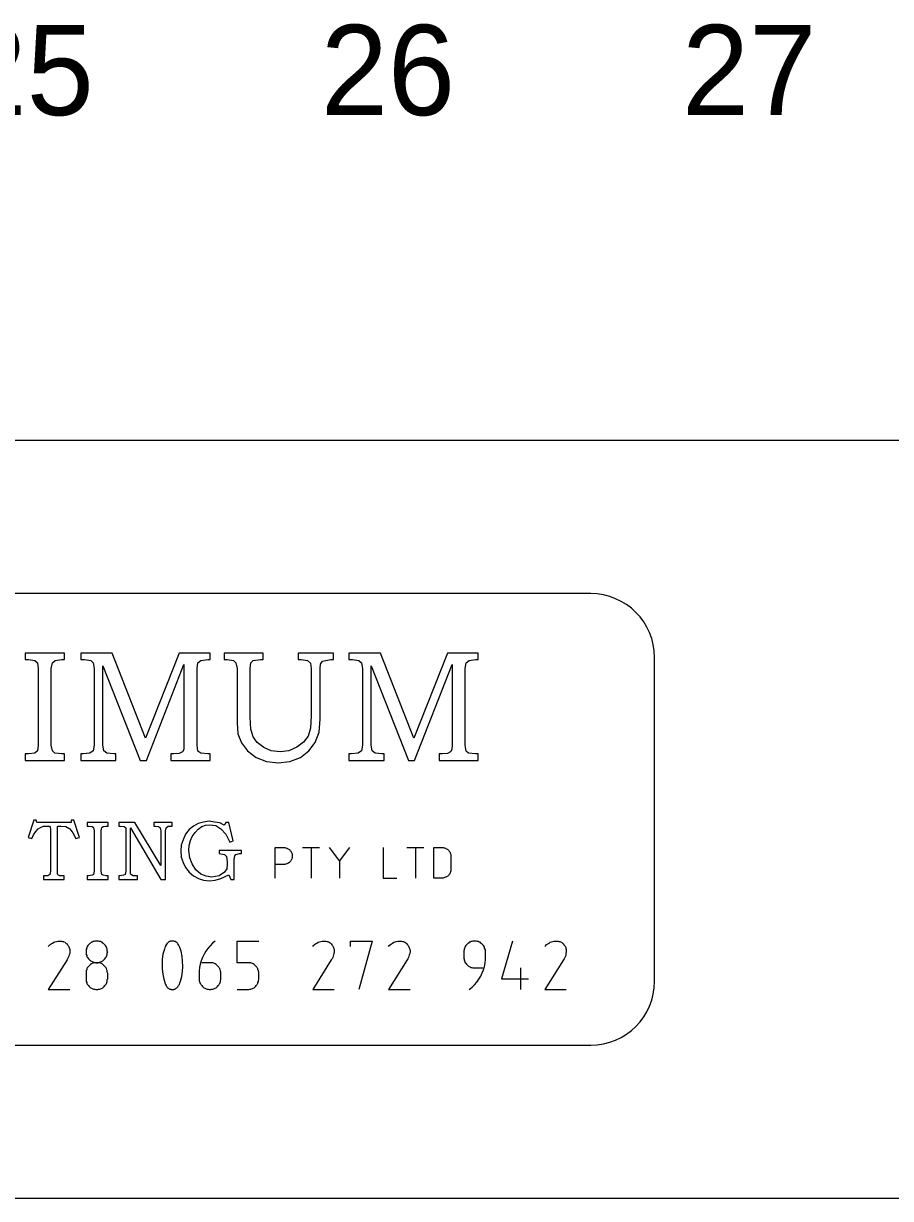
# Model space of a CAD drawing. Extents: x 0 to 841, y 0 to 594.
# Drawn here: x 540.1 to 588.1, y 15 to 80.1 of the extents above; entities that cross this region are included whole.
import ezdxf

# ---------------------------------------------------------------- set-up
doc = ezdxf.new("R2010")
doc.units = 0
for name, color, linetype in [('A1BORDER', 7, 'Continuous'), ('Level 1', 7, 'Continuous'), ('Level 10', 7, 'Continuous')]:
    doc.layers.add(name, color=color, linetype=linetype)

msp = doc.modelspace()

# ---------------------------------------------------------------- linework, layer by layer
at = {"layer": 'A1BORDER'}
for p, q in [((28, 57), (829, 57)), ((829, 15), (28, 15))]:
    msp.add_line(p, q, dxfattribs=at)
at = {"layer": 'Level 1'}
for points in [[(540.64, 35.95), (540.32, 35), (540.52, 34.93), (540.62, 35.15), (540.74, 35.33), (540.87, 35.47), (541, 35.55), (541.17, 35.63), (541.38, 35.63), (541.49, 35.63), (541.53, 35.57), (541.56, 35.45), (541.56, 33.13), (541.52, 32.95), (541.4, 32.87), (541.16, 32.87), (541.16, 32.67), (542.32, 32.67), (542.32, 32.87), (542.08, 32.87), (541.99, 32.9), (541.94, 32.97), (541.94, 33.13), (541.94, 35.43), (541.94, 35.6), (541.97, 35.63), (542.12, 35.63), (542.4, 35.6), (542.63, 35.47), (542.8, 35.25), (542.96, 34.93), (543.16, 35), (542.84, 35.95), (542.7, 35.95), (542.69, 35.83), (540.79, 35.83), (540.77, 35.95)], [(543.59, 35.83), (543.59, 35.63), (543.68, 35.63), (543.87, 35.6), (543.94, 35.55), (543.97, 35.37), (543.97, 33.13), (543.94, 32.95), (543.87, 32.9), (543.68, 32.87), (543.59, 32.87), (543.59, 32.67), (544.74, 32.67), (544.74, 32.87), (544.64, 32.87), (544.47, 32.9), (544.39, 32.95), (544.36, 33.13), (544.36, 35.37), (544.39, 35.55), (544.47, 35.6), (544.64, 35.63), (544.74, 35.63), (544.74, 35.83)], [(545.34, 35.83), (545.34, 35.63), (545.42, 35.63), (545.64, 35.6), (545.72, 35.53), (545.73, 35.37), (545.73, 33.13), (545.69, 32.95), (545.6, 32.9), (545.39, 32.87), (545.34, 32.87), (545.34, 32.67), (546.37, 32.67), (546.37, 32.87), (546.14, 32.87), (546.04, 32.93), (545.99, 32.97), (545.98, 33.13), (545.98, 35.53), (547.66, 32.67), (547.92, 32.67), (547.92, 35.37), (547.96, 35.53), (548.06, 35.63), (548.24, 35.63), (548.29, 35.63), (548.29, 35.83), (547.27, 35.83), (547.27, 35.63), (547.36, 35.63), (547.53, 35.6), (547.62, 35.53), (547.66, 35.37), (547.66, 33.45), (546.23, 35.83)], [(551.26, 35.83), (551.16, 35.67), (550.93, 35.8), (550.64, 35.85), (550.33, 35.9), (550.02, 35.85), (549.73, 35.77), (549.47, 35.63), (549.23, 35.43), (549.03, 35.17), (548.89, 34.87), (548.79, 34.57), (548.77, 34.25), (548.79, 33.9), (548.89, 33.6), (549.03, 33.33), (549.24, 33.07), (549.48, 32.87), (549.74, 32.73), (550.03, 32.63), (550.36, 32.6), (550.67, 32.63), (550.99, 32.73), (551.42, 32.93), (551.54, 32.67), (551.73, 32.67), (551.73, 33.77), (551.76, 33.97), (551.82, 34.05), (552.02, 34.1), (552.12, 34.1), (552.12, 34.27), (550.89, 34.27), (550.89, 34.1), (551.19, 34.05), (551.3, 33.95), (551.34, 33.67), (551.34, 33.53), (551.32, 33.25), (551.19, 33.07), (550.89, 32.87), (550.69, 32.83), (550.48, 32.8), (550.17, 32.85), (549.87, 32.97), (549.6, 33.2), (549.39, 33.53), (549.27, 33.87), (549.22, 34.27), (549.24, 34.55), (549.3, 34.83), (549.4, 35.05), (549.56, 35.27), (549.73, 35.45), (549.93, 35.6), (550.14, 35.67), (550.38, 35.7), (550.7, 35.65), (550.99, 35.47), (551.26, 35.17), (551.48, 34.73), (551.67, 34.8), (551.42, 35.83)]]:
    msp.add_lwpolyline(points, close=True, dxfattribs=at)
for points in [[(554, 32.75), (554, 34.44), (554.48, 34.44), (554.52, 34.44), (554.56, 34.43), (554.59, 34.43), (554.64, 34.41), (554.67, 34.39), (554.7, 34.37), (554.74, 34.35), (554.78, 34.33), (554.8, 34.3), (554.83, 34.26), (554.86, 34.24), (554.88, 34.2), (554.9, 34.16), (554.92, 34.13), (554.93, 34.09), (554.94, 34.05), (554.94, 34.01), (554.94, 33.97), (554.94, 33.93), (554.94, 33.89), (554.93, 33.85), (554.92, 33.81), (554.9, 33.77), (554.88, 33.74), (554.86, 33.7), (554.83, 33.67), (554.8, 33.64), (554.78, 33.61), (554.74, 33.59), (554.7, 33.56), (554.67, 33.55), (554.64, 33.53), (554.59, 33.51), (554.56, 33.51), (554.52, 33.5), (554.48, 33.5), (554, 33.5)], [(555.5, 34.44), (556.44, 34.44)], [(555.98, 34.44), (555.98, 32.75)], [(556.99, 34.44), (557.56, 33.69), (558.12, 34.44)], [(559.98, 34.44), (559.98, 32.75), (560.73, 32.75)], [(561.29, 34.44), (562.23, 34.44)], [(561.77, 34.44), (561.77, 32.75)], [(562.78, 32.75), (562.78, 34.44), (563.26, 34.44), (563.29, 34.44), (563.33, 34.43), (563.37, 34.43), (563.42, 34.41), (563.44, 34.39), (563.48, 34.37), (563.52, 34.35), (563.56, 34.33), (563.58, 34.3), (563.6, 34.26), (563.63, 34.24), (563.66, 34.2), (563.68, 34.16), (563.69, 34.13), (563.7, 34.09), (563.72, 34.05), (563.72, 34.01), (563.72, 33.97), (563.72, 33.23), (563.72, 33.17), (563.72, 33.14), (563.7, 33.1), (563.69, 33.06), (563.68, 33.03), (563.66, 32.99), (563.63, 32.95), (563.6, 32.93), (563.58, 32.89), (563.56, 32.86), (563.52, 32.84), (563.48, 32.81), (563.44, 32.8), (563.42, 32.79), (563.37, 32.77), (563.33, 32.76), (563.29, 32.75), (563.26, 32.75), (562.78, 32.75)], [(557.56, 33.69), (557.56, 32.75)], [(541.43, 28.96), (541.48, 29.01), (541.53, 29.07), (541.59, 29.11), (541.67, 29.15), (541.73, 29.19), (541.8, 29.21), (541.88, 29.24), (541.96, 29.25), (542.03, 29.26), (542.07, 29.26), (542.12, 29.26), (542.17, 29.25), (542.22, 29.24), (542.27, 29.23), (542.3, 29.21), (542.36, 29.19), (542.39, 29.16), (542.43, 29.13), (542.47, 29.1), (542.49, 29.05), (542.53, 29.01), (542.56, 28.97), (542.57, 28.94), (542.59, 28.89), (542.6, 28.84), (542.62, 28.79), (542.62, 28.75), (542.62, 28.7), (542.62, 28.66), (542.62, 28.57), (542.59, 28.5), (542.57, 28.43), (542.54, 28.35), (542.5, 28.27), (542.48, 28.21), (541.43, 26.57), (542.62, 26.57)], [(544.12, 28.06), (544.17, 28.06), (544.22, 28.07), (544.27, 28.09), (544.32, 28.1), (544.37, 28.13), (544.42, 28.15), (544.46, 28.17), (544.49, 28.2), (544.53, 28.24), (544.57, 28.27), (544.6, 28.33), (544.63, 28.36), (544.66, 28.41), (544.68, 28.46), (544.69, 28.51), (544.7, 28.56), (544.7, 28.61), (544.72, 28.66), (544.7, 28.71), (544.7, 28.77), (544.69, 28.81), (544.68, 28.86), (544.66, 28.91), (544.63, 28.96), (544.6, 29.01), (544.57, 29.05), (544.53, 29.09), (544.49, 29.13), (544.46, 29.15), (544.42, 29.19), (544.37, 29.2), (544.32, 29.23), (544.27, 29.24), (544.22, 29.25), (544.17, 29.26), (544.12, 29.26), (544.07, 29.26), (544, 29.25), (543.96, 29.24), (543.9, 29.23), (543.86, 29.2), (543.82, 29.19), (543.77, 29.15), (543.73, 29.13), (543.69, 29.09), (543.66, 29.05), (543.62, 29.01), (543.59, 28.96), (543.57, 28.91), (543.56, 28.86), (543.53, 28.81), (543.53, 28.77), (543.52, 28.71), (543.52, 28.66), (543.52, 28.61), (543.53, 28.56), (543.53, 28.51), (543.56, 28.46), (543.57, 28.41), (543.59, 28.36), (543.62, 28.33), (543.66, 28.27), (543.69, 28.24), (543.73, 28.2), (543.77, 28.17), (543.82, 28.15), (543.86, 28.13), (543.9, 28.1), (543.96, 28.09), (544, 28.07), (544.07, 28.06), (544.12, 28.06)], [(548, 26.73), (548.02, 26.7), (548.04, 26.67), (548.07, 26.65), (548.09, 26.64), (548.12, 26.61), (548.16, 26.6), (548.18, 26.59), (548.22, 26.59), (548.24, 26.57), (548.28, 26.57), (548.3, 26.57), (548.34, 26.57), (548.38, 26.57), (548.4, 26.59), (548.43, 26.6), (548.47, 26.61), (548.49, 26.63), (548.52, 26.65), (548.54, 26.66), (548.57, 26.69), (548.59, 26.71), (548.6, 26.73), (548.64, 26.79), (548.69, 26.86), (548.72, 26.94), (548.76, 27.03), (548.82, 27.3), (548.86, 27.57), (548.88, 27.85), (548.87, 28.14), (548.84, 28.41), (548.78, 28.69), (548.76, 28.81), (548.72, 28.9), (548.68, 28.97), (548.64, 29.05), (548.6, 29.11), (548.58, 29.14), (548.56, 29.16), (548.53, 29.19), (548.5, 29.2), (548.48, 29.23), (548.44, 29.24), (548.42, 29.24), (548.38, 29.25), (548.36, 29.26), (548.32, 29.26), (548.29, 29.26), (548.26, 29.26), (548.23, 29.25), (548.19, 29.25), (548.17, 29.24), (548.13, 29.23), (548.1, 29.21), (548.08, 29.19), (548.06, 29.17), (548.03, 29.15), (548, 29.13), (548, 29.11), (547.96, 29.05), (547.9, 28.96), (547.88, 28.89), (547.86, 28.81), (547.78, 28.54), (547.74, 28.26), (547.73, 27.97), (547.73, 27.7), (547.77, 27.43), (547.82, 27.15), (547.86, 27.03), (547.88, 26.94), (547.92, 26.86), (547.96, 26.79), (548, 26.73)], [(550.68, 29.26), (550.53, 29.14), (550.39, 29), (550.27, 28.85), (550.16, 28.7), (550.06, 28.53), (549.97, 28.35), (549.9, 28.16), (549.84, 27.97), (549.8, 27.79), (549.79, 27.6), (549.79, 27.47), (549.79, 27.17), (549.79, 27.13), (549.79, 27.06), (549.8, 27.01), (549.83, 26.96), (549.84, 26.91), (549.87, 26.87), (549.89, 26.83), (549.93, 26.79), (549.97, 26.75), (550, 26.71), (550.04, 26.67), (550.09, 26.65), (550.13, 26.63), (550.18, 26.61), (550.23, 26.59), (550.28, 26.59), (550.33, 26.57), (550.39, 26.57), (550.44, 26.57), (550.49, 26.59), (550.54, 26.59), (550.59, 26.61), (550.64, 26.63), (550.68, 26.65), (550.73, 26.67), (550.77, 26.71), (550.8, 26.75), (550.84, 26.79), (550.88, 26.83), (550.9, 26.87), (550.93, 26.91), (550.94, 26.96), (550.97, 27.01), (550.97, 27.06), (550.98, 27.13), (550.98, 27.17), (550.98, 27.47), (550.98, 27.53), (550.97, 27.57), (550.97, 27.63), (550.94, 27.67), (550.93, 27.73), (550.9, 27.77), (550.88, 27.81), (550.84, 27.85), (550.8, 27.89), (550.77, 27.93), (550.73, 27.96), (550.68, 27.99), (550.64, 28.01), (550.59, 28.03), (550.54, 28.05), (550.49, 28.06), (550.44, 28.06), (550.39, 28.06), (549.94, 28.06)], [(551.89, 26.57), (552.49, 26.57), (552.54, 26.57), (552.59, 26.59), (552.64, 26.59), (552.69, 26.61), (552.74, 26.63), (552.78, 26.65), (552.83, 26.67), (552.87, 26.71), (552.9, 26.75), (552.94, 26.79), (552.98, 26.83), (553, 26.87), (553.03, 26.91), (553.04, 26.96), (553.07, 27.01), (553.07, 27.06), (553.08, 27.13), (553.08, 27.17), (553.08, 27.47), (553.08, 27.53), (553.07, 27.57), (553.07, 27.63), (553.04, 27.67), (553.03, 27.73), (553, 27.77), (552.98, 27.81), (552.94, 27.85), (552.9, 27.89), (552.87, 27.93), (552.83, 27.96), (552.78, 27.99), (552.74, 28.01), (552.69, 28.03), (552.64, 28.05), (552.59, 28.06), (552.54, 28.06), (552.49, 28.06), (551.89, 28.06), (551.89, 29.26), (553.08, 29.26)], [(556.07, 28.96), (556.12, 29.01), (556.17, 29.07), (556.23, 29.11), (556.3, 29.15), (556.37, 29.19), (556.44, 29.21), (556.52, 29.24), (556.59, 29.25), (556.67, 29.26), (556.7, 29.26), (556.76, 29.26), (556.8, 29.25), (556.86, 29.24), (556.9, 29.23), (556.94, 29.21), (556.99, 29.19), (557.03, 29.16), (557.07, 29.13), (557.1, 29.1), (557.13, 29.05), (557.17, 29.01), (557.19, 28.97), (557.2, 28.94), (557.23, 28.89), (557.24, 28.84), (557.26, 28.79), (557.26, 28.75), (557.26, 28.7), (557.26, 28.66), (557.24, 28.57), (557.23, 28.5), (557.2, 28.43), (557.18, 28.35), (557.14, 28.27), (557.1, 28.21), (556.07, 26.57), (557.26, 26.57)], [(558.17, 28.96), (558.17, 29.26), (559.36, 29.26), (558.62, 26.57)], [(560.26, 28.96), (560.3, 29.01), (560.37, 29.07), (560.43, 29.11), (560.49, 29.15), (560.56, 29.19), (560.63, 29.21), (560.7, 29.24), (560.78, 29.25), (560.86, 29.26), (560.89, 29.26), (560.94, 29.26), (560.99, 29.25), (561.04, 29.24), (561.09, 29.23), (561.13, 29.21), (561.18, 29.19), (561.22, 29.16), (561.26, 29.13), (561.29, 29.1), (561.32, 29.05), (561.36, 29.01), (561.38, 28.97), (561.4, 28.94), (561.42, 28.89), (561.43, 28.84), (561.44, 28.79), (561.46, 28.75), (561.46, 28.7), (561.46, 28.66), (561.44, 28.57), (561.42, 28.5), (561.39, 28.43), (561.37, 28.35), (561.33, 28.27), (561.3, 28.21), (560.26, 26.57), (561.46, 26.57)], [(564.74, 26.57), (564.89, 26.7), (565.03, 26.84), (565.16, 26.99), (565.27, 27.14), (565.37, 27.31), (565.46, 27.49), (565.52, 27.66), (565.58, 27.85), (565.62, 28.05), (565.63, 28.24), (565.63, 28.36), (565.63, 28.66), (565.63, 28.71), (565.63, 28.77), (565.62, 28.81), (565.59, 28.86), (565.58, 28.91), (565.56, 28.96), (565.53, 29.01), (565.49, 29.05), (565.46, 29.09), (565.42, 29.13), (565.38, 29.15), (565.34, 29.19), (565.29, 29.2), (565.24, 29.23), (565.19, 29.24), (565.14, 29.25), (565.09, 29.26), (565.04, 29.26), (564.98, 29.26), (564.93, 29.25), (564.88, 29.24), (564.83, 29.23), (564.78, 29.2), (564.74, 29.19), (564.69, 29.15), (564.66, 29.13), (564.62, 29.09), (564.58, 29.05), (564.54, 29.01), (564.52, 28.96), (564.49, 28.91), (564.48, 28.86), (564.46, 28.81), (564.46, 28.77), (564.44, 28.71), (564.44, 28.66), (564.44, 28.36), (564.44, 28.31), (564.46, 28.26), (564.46, 28.21), (564.48, 28.16), (564.49, 28.11), (564.52, 28.06), (564.54, 28.03), (564.58, 27.97), (564.62, 27.94), (564.66, 27.91), (564.69, 27.87), (564.74, 27.85), (564.78, 27.83), (564.83, 27.8), (564.88, 27.79), (564.93, 27.77), (564.98, 27.77), (565.04, 27.77), (565.49, 27.77)], [(567.13, 29.26), (566.53, 27.17), (568.02, 27.17)], [(568.92, 28.96), (568.97, 29.01), (569.02, 29.07), (569.08, 29.11), (569.16, 29.15), (569.22, 29.19), (569.29, 29.21), (569.37, 29.24), (569.44, 29.25), (569.52, 29.26), (569.56, 29.26), (569.6, 29.26), (569.66, 29.25), (569.7, 29.24), (569.76, 29.23), (569.79, 29.21), (569.84, 29.19), (569.88, 29.16), (569.92, 29.13), (569.96, 29.1), (569.98, 29.05), (570.02, 29.01), (570.04, 28.97), (570.06, 28.94), (570.08, 28.89), (570.09, 28.84), (570.1, 28.79), (570.1, 28.75), (570.1, 28.7), (570.1, 28.66), (570.09, 28.57), (570.08, 28.5), (570.06, 28.43), (570.03, 28.35), (569.99, 28.27), (569.96, 28.21), (568.92, 26.57), (570.1, 26.57)], [(543.52, 27.17), (543.52, 27.13), (543.53, 27.06), (543.53, 27.01), (543.56, 26.96), (543.57, 26.91), (543.59, 26.87), (543.62, 26.83), (543.66, 26.79), (543.69, 26.75), (543.73, 26.71), (543.77, 26.67), (543.82, 26.65), (543.86, 26.63), (543.9, 26.61), (543.96, 26.59), (544, 26.59), (544.07, 26.57), (544.12, 26.57), (544.17, 26.57), (544.22, 26.59), (544.27, 26.59), (544.32, 26.61), (544.37, 26.63), (544.42, 26.65), (544.46, 26.67), (544.49, 26.71), (544.53, 26.75), (544.57, 26.79), (544.6, 26.83), (544.63, 26.87), (544.66, 26.91), (544.68, 26.96), (544.69, 27.01), (544.7, 27.06), (544.7, 27.13), (544.72, 27.17), (544.72, 27.47), (544.7, 27.53), (544.7, 27.57), (544.69, 27.63), (544.68, 27.67), (544.66, 27.73), (544.63, 27.77), (544.6, 27.81), (544.57, 27.85), (544.53, 27.89), (544.49, 27.93), (544.46, 27.96), (544.42, 27.99), (544.37, 28.01), (544.32, 28.03), (544.27, 28.05), (544.22, 28.06), (544.17, 28.06), (544.12, 28.06), (544.07, 28.06), (544, 28.06), (543.96, 28.05), (543.9, 28.03), (543.86, 28.01), (543.82, 27.99), (543.77, 27.96), (543.73, 27.93), (543.69, 27.89), (543.66, 27.85), (543.62, 27.81), (543.59, 27.77), (543.57, 27.73), (543.56, 27.67), (543.53, 27.63), (543.53, 27.57), (543.52, 27.53), (543.52, 27.47), (543.52, 27.17)], [(567.58, 27.77), (567.58, 26.57)]]:
    msp.add_lwpolyline(points, dxfattribs=at)
at = {"layer": 'Level 10'}
for p, q in [((571.47, 48.5), (513.54, 48.5)), ((575, 27.03), (575, 44.97)), ((513.54, 23.5), (571.47, 23.5))]:
    msp.add_line(p, q, dxfattribs=at)
for points in [[(540.16, 45.2), (540.16, 44.85), (540.33, 44.85), (540.69, 44.8), (540.83, 44.67), (540.88, 44.35), (540.88, 40.1), (540.83, 39.8), (540.69, 39.67), (540.33, 39.63), (540.16, 39.63), (540.16, 39.25), (542.33, 39.25), (542.33, 39.63), (542.16, 39.63), (541.8, 39.67), (541.66, 39.8), (541.6, 40.1), (541.6, 44.35), (541.66, 44.67), (541.82, 44.8), (542.16, 44.85), (542.33, 44.85), (542.33, 45.2)], [(543.23, 45.2), (543.23, 44.85), (543.43, 44.85), (543.78, 44.8), (543.92, 44.67), (543.98, 44.35), (543.98, 40.1), (543.92, 39.8), (543.74, 39.67), (543.36, 39.63), (543.23, 39.63), (543.23, 39.25), (545.18, 39.25), (545.18, 39.63), (545.06, 39.63), (544.67, 39.67), (544.5, 39.8), (544.46, 40.1), (544.46, 44.5), (546.52, 39.25), (546.86, 39.25), (548.94, 44.57), (548.94, 40.1), (548.93, 39.87), (548.86, 39.73), (548.68, 39.65), (548.38, 39.63), (548.22, 39.63), (548.22, 39.25), (550.39, 39.25), (550.39, 39.63), (550.26, 39.63), (549.87, 39.67), (549.72, 39.77), (549.67, 40.1), (549.67, 44.35), (549.72, 44.67), (549.88, 44.8), (550.26, 44.85), (550.39, 44.85), (550.39, 45.2), (548.68, 45.2), (546.82, 40.5), (544.97, 45.2)], [(551.16, 45.2), (551.16, 44.85), (551.34, 44.85), (551.68, 44.8), (551.82, 44.67), (551.88, 44.35), (551.88, 41.35), (551.93, 40.73), (552.13, 40.23), (552.46, 39.8), (552.94, 39.43), (553.52, 39.2), (554.16, 39.13), (554.8, 39.2), (555.39, 39.43), (555.86, 39.8), (556.2, 40.25), (556.42, 40.83), (556.49, 41.55), (556.49, 44.35), (556.5, 44.6), (556.62, 44.75), (556.79, 44.8), (557.07, 44.85), (557.22, 44.85), (557.22, 45.2), (555.27, 45.2), (555.27, 44.85), (555.43, 44.85), (555.78, 44.8), (555.94, 44.65), (555.99, 44.35), (555.99, 41.73), (555.94, 41.05), (555.82, 40.6), (555.57, 40.27), (555.2, 40), (554.74, 39.8), (554.27, 39.73), (553.78, 39.8), (553.36, 39.97), (553, 40.25), (552.78, 40.57), (552.64, 41), (552.6, 41.65), (552.6, 44.35), (552.64, 44.67), (552.78, 44.8), (553.18, 44.85), (553.33, 44.85), (553.33, 45.2)], [(558.08, 45.2), (558.08, 44.85), (558.28, 44.85), (558.63, 44.8), (558.77, 44.67), (558.82, 44.35), (558.82, 40.1), (558.77, 39.8), (558.59, 39.67), (558.2, 39.63), (558.08, 39.63), (558.08, 39.25), (560.03, 39.25), (560.03, 39.63), (559.9, 39.63), (559.52, 39.67), (559.36, 39.8), (559.3, 40.1), (559.3, 44.5), (561.37, 39.25), (561.7, 39.25), (563.79, 44.57), (563.79, 40.1), (563.77, 39.87), (563.7, 39.73), (563.53, 39.65), (563.23, 39.63), (563.07, 39.63), (563.07, 39.25), (565.24, 39.25), (565.24, 39.63), (565.09, 39.63), (564.7, 39.67), (564.57, 39.77), (564.52, 40.1), (564.52, 44.35), (564.57, 44.67), (564.73, 44.8), (565.09, 44.85), (565.24, 44.85), (565.24, 45.2), (563.53, 45.2), (561.67, 40.5), (559.82, 45.2)]]:
    msp.add_lwpolyline(points, close=True, dxfattribs=at)
for centre, start, end in [((571.465, 44.963), 0, 90), ((571.465, 27.03), 270, 0)]:
    msp.add_arc(centre, 3.535, start, end, dxfattribs=at)

# ---------------------------------------------------------------- texts
at = {"layer": 'Level 1'}
for s, p in [('25', (536.517, 75)), ('26', (556.517, 75)), ('27', (576.517, 75))]:
    msp.add_text(s, height=5, dxfattribs=at).set_placement(p)

doc.saveas('drawing.dxf')
